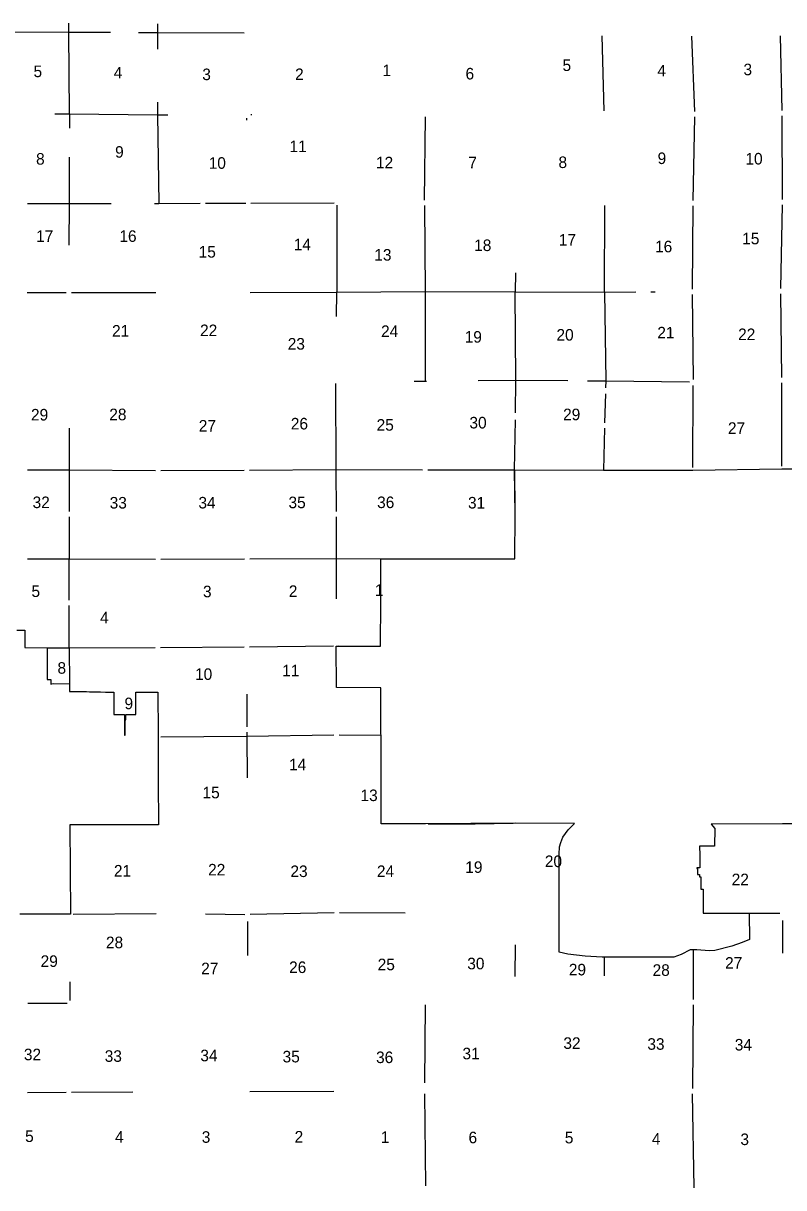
# Model space of a CAD drawing. Extents: x -2933025 to 31692252, y -2344676 to 23854604.
# Drawn here: x -2120944 to -2098390, y -2188374 to -2153831 of the extents above; entities that cross this region are included whole.
import ezdxf

# ---------------------------------------------------------------- set-up
doc = ezdxf.new("R2010")
doc.units = 0
for name, color, linetype in [('tdCoCorpBndry', 7, 'Continuous'), ('tdCoSectLinePart', 7, 'Continuous'), ('tdCoSectNmbr', 7, 'Continuous')]:
    doc.layers.add(name, color=color, linetype=linetype)

msp = doc.modelspace()

# ---------------------------------------------------------------- linework, layer by layer
at = {"layer": 'tdCoCorpBndry'}
for points in [[(-2095744, -2177578), (-2098426, -2177581), (-2100543, -2177591), (-2100437, -2177720), (-2100439, -2178237), (-2100884, -2178239), (-2100882, -2178510), (-2100882, -2178528), (-2100882, -2178569), (-2100881, -2178665), (-2100881, -2178745), (-2100881, -2178889), (-2100965, -2178888), (-2100965, -2178905), (-2100948, -2178905), (-2100948, -2179078), (-2100885, -2179078), (-2100885, -2179153), (-2100849, -2179153), (-2100848, -2179519), (-2100778, -2179519), (-2100778, -2180227), (-2099415, -2180226), (-2099407, -2181007), (-2099619, -2181101), (-2099932, -2181208), (-2100431, -2181340), (-2100600, -2181349), (-2100963, -2181312), (-2101074, -2181314), (-2101167, -2181315), (-2101427, -2181454), (-2101645, -2181538), (-2103702, -2181531), (-2103778, -2181533), (-2104283, -2181502), (-2104790, -2181442), (-2105047, -2181388), (-2105054, -2178774), (-2105051, -2178475), (-2105038, -2178261), (-2104999, -2178128), (-2104937, -2177977), (-2104859, -2177865), (-2104779, -2177758), (-2104597, -2177572), (-2106332, -2177558), (-2109018, -2177584), (-2110331, -2177576), (-2110332, -2176268), (-2110337, -2173595), (-2110337, -2173549), (-2111654, -2173538), (-2111659, -2172304), (-2110350, -2172307), (-2110344, -2170984), (-2110339, -2169713), (-2109019, -2169715), (-2106365, -2169719), (-2106359, -2168389), (-2106370, -2167074), (-2103735, -2167092), (-2101500, -2167085), (-2101418, -2167089), (-2101085, -2167084), (-2098443, -2167049), (-2097716, -2167048)], [(-2121136, -2171829), (-2120896, -2171829), (-2120897, -2172344), (-2120233, -2172354), (-2120234, -2173296), (-2120128, -2173296), (-2120127, -2173435), (-2120095, -2173424), (-2120058, -2173420), (-2119575, -2173422), (-2119574, -2173656), (-2119421, -2173656), (-2119393, -2173655), (-2119254, -2173655), (-2119230, -2173655), (-2119170, -2173656), (-2119073, -2173657), (-2118984, -2173661), (-2118895, -2173664), (-2118809, -2173665), (-2118654, -2173667), (-2118509, -2173670), (-2118467, -2173671), (-2118303, -2173675), (-2118262, -2173675), (-2118262, -2174336), (-2117942, -2174337), (-2117942, -2174949), (-2117924, -2174947), (-2117924, -2174491), (-2117904, -2174491), (-2117904, -2174338), (-2117607, -2174338), (-2117606, -2173676), (-2117084, -2173674), (-2116956, -2173675), (-2116948, -2174896), (-2116946, -2175020), (-2116945, -2175098), (-2116945, -2175106), (-2116944, -2175273), (-2116944, -2175285), (-2116944, -2175297), (-2116939, -2176302), (-2116932, -2177605), (-2118884, -2177606), (-2119562, -2177607), (-2119545, -2180258), (-2120856, -2180260), (-2121042, -2180259)]]:
    msp.add_lwpolyline(points, dxfattribs=at)
at = {"layer": 'tdCoSectLinePart'}
for points in [[(-2122172, -2154082), (-2119594, -2154090)], [(-2119594, -2154090), (-2119594, -2153831)], [(-2119594, -2154090), (-2118357, -2154098)], [(-2119577, -2156517), (-2119594, -2154090)], [(-2117527, -2154103), (-2116965, -2154106)], [(-2116966, -2153844), (-2116965, -2154106)], [(-2116965, -2154106), (-2116966, -2154596)], [(-2116965, -2154106), (-2114396, -2154115)], [(-2103719, -2156428), (-2103771, -2154203)], [(-2101127, -2154210), (-2101040, -2156445)], [(-2098491, -2154206), (-2098449, -2156419)], [(-2116967, -2156173), (-2116968, -2156544)], [(-2120007, -2156519), (-2119577, -2156517)], [(-2119577, -2156517), (-2119578, -2156944)], [(-2119577, -2156517), (-2116968, -2156544)], [(-2116968, -2156544), (-2116660, -2156543)], [(-2116968, -2156544), (-2116927, -2159173)], [(-2114310, -2156704), (-2114311, -2156650)], [(-2114193, -2156540), (-2114163, -2156539)], [(-2109041, -2159081), (-2109017, -2156602)], [(-2101038, -2156603), (-2101088, -2159083)], [(-2098447, -2156577), (-2098431, -2159061)], [(-2119581, -2157802), (-2119586, -2159173)], [(-2120821, -2159172), (-2119586, -2159173)], [(-2119586, -2159173), (-2119591, -2160415)], [(-2119586, -2159173), (-2118339, -2159173)], [(-2117053, -2159173), (-2116927, -2159173)], [(-2116927, -2159173), (-2115697, -2159170)], [(-2116927, -2159186), (-2116927, -2159173)], [(-2115539, -2159169), (-2114348, -2159166)], [(-2114190, -2159165), (-2111720, -2159153)], [(-2111646, -2159227), (-2111648, -2161791), (-2111650, -2161810)], [(-2109042, -2159239), (-2109029, -2161792)], [(-2103707, -2161804), (-2103696, -2159239)], [(-2101090, -2159241), (-2101104, -2161718)], [(-2098433, -2159220), (-2098483, -2161694)], [(-2106340, -2161232), (-2106355, -2161797)], [(-2120825, -2161818), (-2119677, -2161816)], [(-2119518, -2161816), (-2117009, -2161817)], [(-2114211, -2161813), (-2111650, -2161810)], [(-2111650, -2161810), (-2111660, -2162525)], [(-2111650, -2161810), (-2109029, -2161792)], [(-2109029, -2161792), (-2106355, -2161797)], [(-2109029, -2161792), (-2109020, -2164445)], [(-2106355, -2161797), (-2103707, -2161804)], [(-2106331, -2164413), (-2106355, -2161797)], [(-2103707, -2161804), (-2102778, -2161802)], [(-2103707, -2161804), (-2103669, -2164439)], [(-2102329, -2161801), (-2102200, -2161800)], [(-2101103, -2161877), (-2101080, -2164395)], [(-2098483, -2161852), (-2098452, -2164337)], [(-2109355, -2164443), (-2109020, -2164445)], [(-2109020, -2164445), (-2108985, -2164444)], [(-2109020, -2164453), (-2109020, -2164445)], [(-2107455, -2164426), (-2106331, -2164413)], [(-2106346, -2165385), (-2106331, -2164413)], [(-2106331, -2164413), (-2104795, -2164428)], [(-2104209, -2164434), (-2103669, -2164439)], [(-2103669, -2164439), (-2103675, -2164647)], [(-2103669, -2164439), (-2101188, -2164464)], [(-2111688, -2164515), (-2111670, -2167064)], [(-2101085, -2167005), (-2101079, -2164578)], [(-2098444, -2166970), (-2098450, -2164495)], [(-2103679, -2164825), (-2103701, -2165688)], [(-2119588, -2165838), (-2119579, -2167075)], [(-2106371, -2167074), (-2106349, -2165594)], [(-2103705, -2165846), (-2103736, -2167092)], [(-2120815, -2167074), (-2119579, -2167075)], [(-2119579, -2167075), (-2117027, -2167097)], [(-2119579, -2167075), (-2119579, -2168316)], [(-2116869, -2167098), (-2114388, -2167085)], [(-2114230, -2167084), (-2111670, -2167064)], [(-2111670, -2167064), (-2109103, -2167073)], [(-2111670, -2167064), (-2111666, -2168309)], [(-2108945, -2167074), (-2106371, -2167074)], [(-2106371, -2167074), (-2106368, -2168310)], [(-2101501, -2167085), (-2101165, -2167084)], [(-2119579, -2168474), (-2119579, -2169716)], [(-2111666, -2168468), (-2111662, -2169710)], [(-2120821, -2169720), (-2119579, -2169716)], [(-2119582, -2170946), (-2119579, -2169716)], [(-2119579, -2169716), (-2117021, -2169728)], [(-2116862, -2169728), (-2114386, -2169718)], [(-2114226, -2169717), (-2111662, -2169710)], [(-2111662, -2169710), (-2110340, -2169713)], [(-2111662, -2169710), (-2111661, -2170906)], [(-2119586, -2172361), (-2119583, -2171104)], [(-2120234, -2172354), (-2119586, -2172361)], [(-2119586, -2172361), (-2117037, -2172346)], [(-2119586, -2172361), (-2119577, -2173422)], [(-2116879, -2172345), (-2114395, -2172328)], [(-2114236, -2172326), (-2111739, -2172303)], [(-2111580, -2172302), (-2110351, -2172307)], [(-2114311, -2173735), (-2114309, -2174701)], [(-2116868, -2174997), (-2114309, -2174977)], [(-2114309, -2174859), (-2114309, -2174977)], [(-2114309, -2174977), (-2111734, -2174940)], [(-2114309, -2174977), (-2114307, -2176219)], [(-2111576, -2174940), (-2110335, -2174945)], [(-2108940, -2177584), (-2107660, -2177581), (-2107546, -2177580), (-2106413, -2177560)], [(-2119467, -2180257), (-2117000, -2180241)], [(-2115535, -2180253), (-2114369, -2180264)], [(-2114211, -2180263), (-2111727, -2180210)], [(-2111569, -2180209), (-2109620, -2180219)], [(-2099416, -2180226), (-2098509, -2180225)], [(-2114290, -2180475), (-2114290, -2181485)], [(-2098430, -2180447), (-2098430, -2181413)], [(-2106358, -2182104), (-2106349, -2181169)], [(-2101073, -2181314), (-2101073, -2182787)], [(-2103702, -2182092), (-2103702, -2181531)], [(-2119561, -2182265), (-2119566, -2182818)], [(-2120811, -2182899), (-2119645, -2182897)], [(-2109037, -2185262), (-2109019, -2182944)], [(-2101074, -2182946), (-2101092, -2185433)], [(-2119514, -2185541), (-2117692, -2185531)], [(-2114226, -2185520), (-2111737, -2185513)], [(-2120820, -2185545), (-2119672, -2185542)], [(-2109008, -2188318), (-2109038, -2185587)], [(-2101041, -2188374), (-2101091, -2185592)]]:
    msp.add_lwpolyline(points, dxfattribs=at)

# ---------------------------------------------------------------- texts
at = {"layer": 'tdCoSectNmbr'}
for s, height, rotation, p in [('5', 343, 0.0065, (-2120640, -2155428)), ('4', 343, 0.0072, (-2118261, -2155466)), ('1', 343, 0.0095, (-2110292, -2155399)), ('5', 343, 0.0139, (-2104950, -2155246)), ('4', 343, 0.0147, (-2102137, -2155407)), ('3', 343, 0.0154, (-2099583, -2155372)), ('3', 343, 0.0079, (-2115635, -2155517)), ('2', 343, 0.0087, (-2112883, -2155515)), ('6', 343, 0.0102, (-2107827, -2155497)), ('9', 343, 0.0072, (-2118221, -2157818)), ('11', 343.2, 0.0087, (-2113048, -2157652)), ('8', 343, 0.0065, (-2120565, -2158025)), ('10', 343.2, 0.008, (-2115445, -2158147)), ('12', 343.2, 0.0094, (-2110483, -2158134)), ('7', 343, 0.0115, (-2107744, -2158135)), ('8', 343, 0.0137, (-2105070, -2158125)), ('9', 343, 0.0146, (-2102130, -2158006)), ('10', 343.2, 0.0154, (-2099526, -2158020)), ('17', 343.2, 0.0065, (-2120564, -2160316)), ('16', 343.2, 0.0072, (-2118094, -2160316)), ('14', 343.2, 0.0087, (-2112923, -2160564)), ('18', 343.2, 0.0129, (-2107571, -2160588)), ('17', 343.2, 0.0136, (-2105060, -2160425)), ('16', 343.2, 0.0144, (-2102206, -2160625)), ('15', 343.2, 0.0152, (-2099621, -2160386)), ('15', 343.2, 0.0079, (-2115743, -2160782)), ('13', 343.2, 0.0094, (-2110533, -2160871)), ('21', 343.2, 0.0071, (-2118312, -2163126)), ('22', 343.2, 0.0079, (-2115701, -2163111)), ('24', 343.2, 0.0094, (-2110333, -2163137)), ('19', 343.2, 0.0107, (-2107852, -2163305)), ('20', 343.2, 0.0135, (-2105130, -2163244)), ('21', 343.2, 0.0144, (-2102139, -2163179)), ('22', 343.2, 0.0151, (-2099743, -2163229)), ('23', 343.2, 0.0086, (-2113101, -2163511)), ('29', 343.2, 0.0065, (-2120716, -2165614)), ('28', 343.2, 0.0071, (-2118393, -2165606)), ('30', 343.2, 0.0118, (-2107712, -2165850)), ('29', 343.2, 0.0135, (-2104934, -2165606)), ('27', 343.2, 0.0079, (-2115739, -2165943)), ('26', 343.2, 0.0085, (-2113009, -2165880)), ('25', 343.2, 0.0094, (-2110464, -2165916)), ('27', 343.2, 0.0149, (-2100044, -2166011)), ('32', 343.2, 0.0064, (-2120668, -2168213)), ('33', 343.2, 0.0071, (-2118382, -2168226)), ('34', 343.2, 0.0078, (-2115750, -2168224)), ('35', 343.2, 0.0085, (-2113078, -2168216)), ('36', 343.2, 0.0094, (-2110450, -2168213)), ('31', 343.2, 0.0101, (-2107754, -2168225)), ('5', 343, 0.0064, (-2120701, -2170850)), ('3', 343, 0.0078, (-2115614, -2170858)), ('2', 343, 0.0086, (-2113069, -2170849)), ('1', 343, 0.0093, (-2110513, -2170816)), ('4', 343, 0.0069, (-2118666, -2171632)), ('8', 343, 0.0066, (-2119930, -2173127)), ('10', 343.2, 0.0078, (-2115850, -2173310)), ('11', 343.2, 0.0085, (-2113265, -2173203)), ('9', 343, 0.0071, (-2117942, -2174179)), ('14', 343.2, 0.0086, (-2113063, -2175992)), ('15', 343.2, 0.0079, (-2115628, -2176822)), ('13', 343.2, 0.0092, (-2110943, -2176905)), ('20', 343.2, 0.0129, (-2105475, -2178862)), ('21', 343.2, 0.0071, (-2118256, -2179143)), ('22', 343.2, 0.0079, (-2115463, -2179111)), ('23', 343.2, 0.0086, (-2113021, -2179158)), ('24', 343.2, 0.0093, (-2110456, -2179157)), ('19', 343.2, 0.0101, (-2107835, -2179035)), ('22', 343.2, 0.0144, (-2099933, -2179401)), ('28', 343.2, 0.0064, (-2118492, -2181269)), ('29', 343.2, 0.0064, (-2120430, -2181824)), ('27', 343.2, 0.0064, (-2115667, -2182041)), ('26', 343.2, 0.0086, (-2113060, -2182005)), ('25', 343.2, 0.0093, (-2110433, -2181922)), ('30', 343.2, 0.0101, (-2107776, -2181895)), ('29', 343.2, 0.0128, (-2104763, -2182075)), ('27', 343.2, 0.0142, (-2100129, -2181877)), ('28', 343.2, 0.0135, (-2102279, -2182089)), ('32', 343.2, 0.0127, (-2104925, -2184256)), ('33', 343.2, 0.0134, (-2102434, -2184282)), ('34', 343.2, 0.0142, (-2099842, -2184304)), ('32', 343.2, 0.0062, (-2120926, -2184593)), ('33', 343.2, 0.007, (-2118529, -2184640)), ('34', 343.2, 0.0078, (-2115693, -2184623)), ('35', 343.2, 0.0085, (-2113253, -2184656)), ('36', 343.2, 0.0093, (-2110481, -2184677)), ('31', 343.2, 0.01, (-2107918, -2184565)), ('5', 343, 0.0062, (-2120890, -2187017)), ('4', 343, 0.007, (-2118220, -2187036)), ('3', 343, 0.0078, (-2115651, -2187042)), ('2', 343, 0.0086, (-2112896, -2187034)), ('1', 343, 0.0093, (-2110341, -2187045)), ('6', 343, 0.01, (-2107738, -2187055)), ('5', 343, 0.0126, (-2104882, -2187058)), ('4', 343, 0.0133, (-2102301, -2187098)), ('3', 343, 0.0141, (-2099674, -2187109))]:
    msp.add_text(s, height=height, rotation=rotation, dxfattribs=at).set_placement(p)

doc.saveas('drawing.dxf')
